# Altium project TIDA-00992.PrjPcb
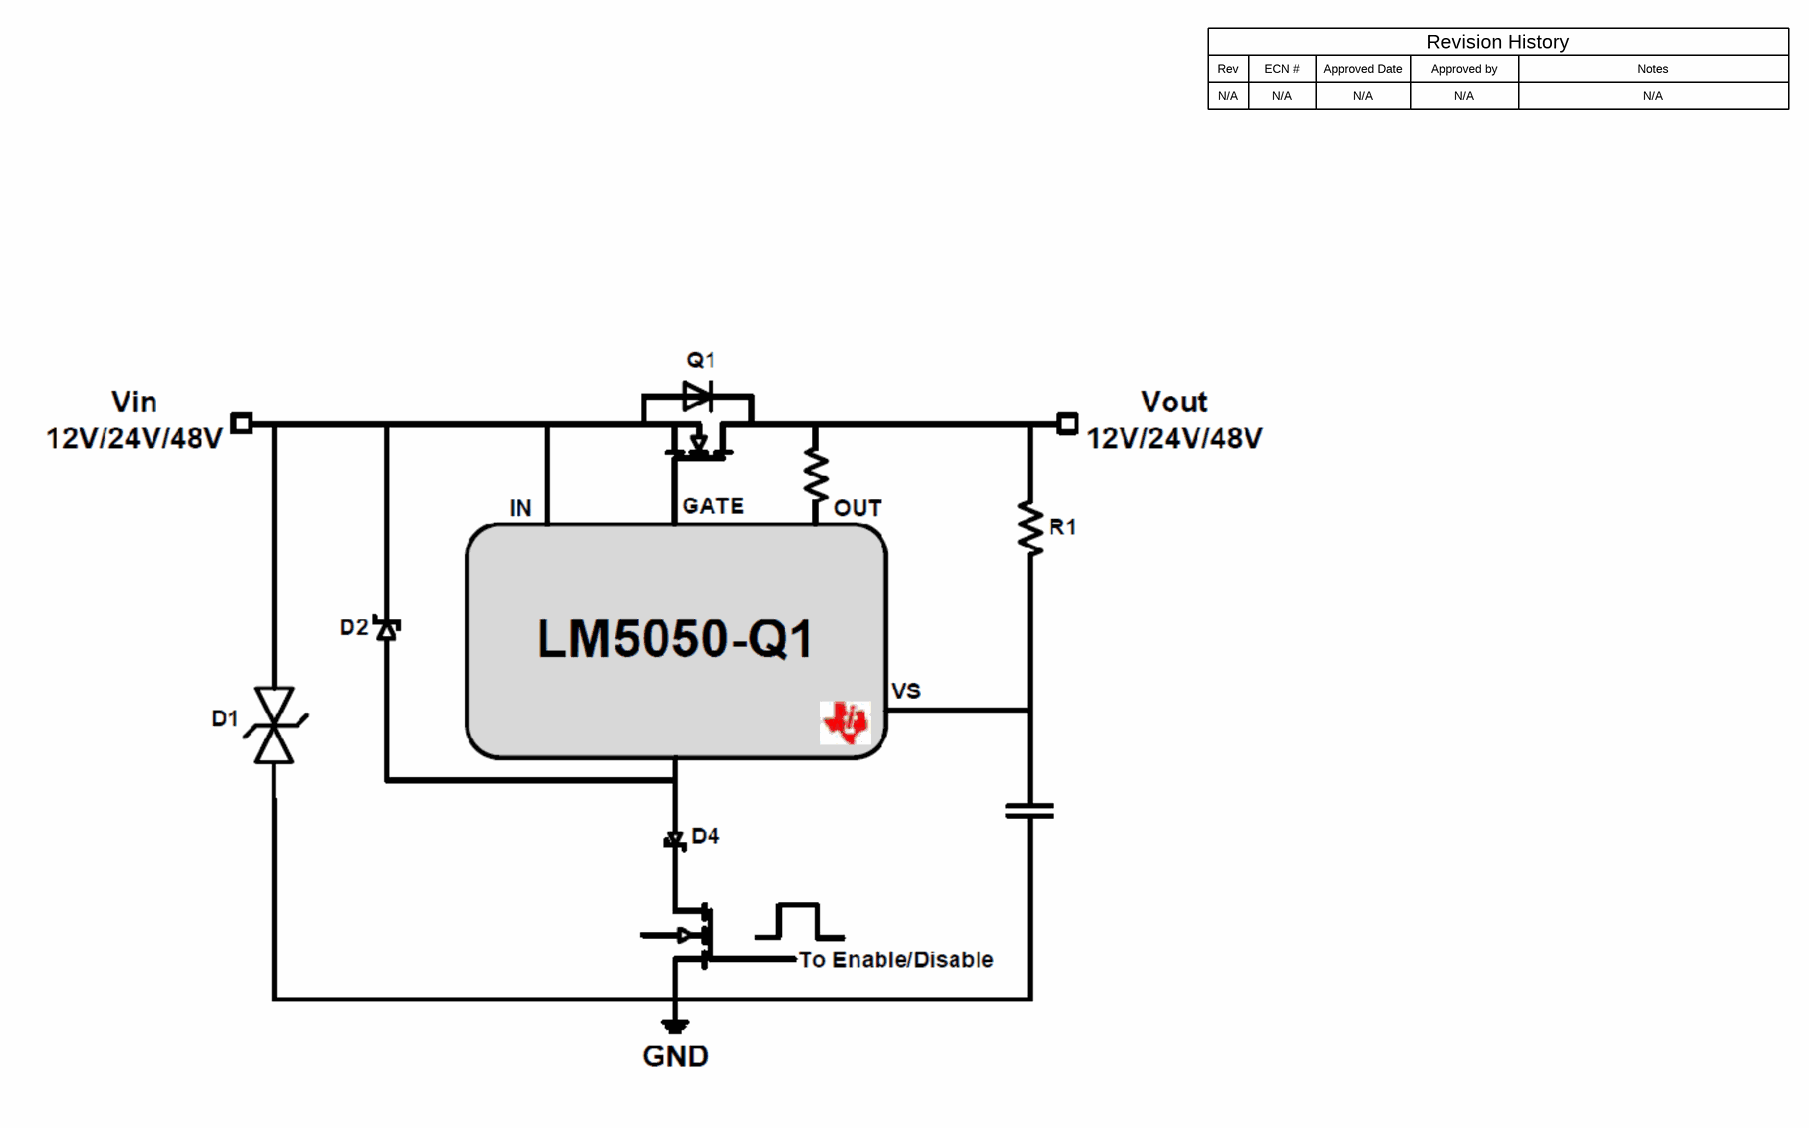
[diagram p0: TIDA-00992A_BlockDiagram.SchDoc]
CopyrightYear: 2016; EVM_orderable: TIDA-00992A; PCB_Layout: Rama Kambham; PCB_Rev: Rev A; PRJ_Customer: Public Release; PRJ_Engineer: Rama Kambham; PRJ_Number: TIDA-00992A; PRJ_Title: Automotive Reverse Polarity Protection; SCH_Rev: Rev A; TechSupport: http://www.ti.com/support; TID: N/A
3 sheets, 33 parts. Net scope: global (net labels, ports and power ports of the same name join across sheets).
Board file: TIDA-00992A_PCB.PcbDoc
Sheets:
  TIDA-00992A_BlockDiagram.SchDoc
  TIDA-00992A_AutomotiveReversePolarityProtection.SchDoc
  TIDA-00992A_Hardware.SchDoc

## Sheet TIDA-00992A_BlockDiagram.SchDoc: Block Diagram
size 431 x 279 mm; Date: Not shown in title block; ApprovedBy: Not shown in title block; CheckedBy: Not shown in title block; Author: Not shown in title block; CompanyName: Not shown in title block; DrawnBy: Rama Kambham; Engineer: Rama Kambham; Organization: Not shown in title block; Address1: Not shown in title block; Address2: Not shown in title block; Address3: Not shown in title block; Address4: Not shown in title block; DocumentNumber: 1; Revision: Use project parameter SCH_Rev; SheetNumber: 1; SheetTotal: 3; PageSetup: Record=PageOptions¦CenterHorizontal=True¦CenterVertical=True¦PrintScale=0.62¦XCorrection=1.00¦YCorrection=1.00¦PrintKind=0¦BorderSize=5000000¦LeftOffset=0¦BottomOffset=0¦Orientation=2¦PaperLength=1000¦PaperWidth=1000¦Scale=100¦PaperSource=15¦PrintQuality=600¦MediaType=1¦DitherType=10¦PrintScaleMode=1¦PaperKind=Letter

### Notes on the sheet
- Rev
- N/A
- ECN #
- Approved Date
- Approved by
- Revision History
- Notes

## Sheet TIDA-00992A_AutomotiveReversePolarityProtection.SchDoc: Schematic
size 431 x 279 mm; Date: Not shown in title block; ApprovedBy: Not shown in title block; CheckedBy: Not shown in title block; Author: Not shown in title block; CompanyName: Not shown in title block; DrawnBy: Rama Kambham; Engineer: Rama Kambham; Organization: Not shown in title block; Address1: Not shown in title block; Address2: Not shown in title block; Address3: Not shown in title block; Address4: Not shown in title block; DocumentNumber: 1; Revision: 01; SheetNumber: 2; SheetTotal: 3; PageSetup: Record=PageOptions¦CenterHorizontal=True¦CenterVertical=True¦PrintScale=1.00¦XCorrection=1.00¦YCorrection=1.00¦PrintKind=0¦BorderSize=5000000¦LeftOffset=0¦BottomOffset=0¦Orientation=2¦PaperLength=1000¦PaperWidth=1000¦Scale=100¦PaperSource=15¦PrintQuality=600¦MediaType=1¦DitherType=10¦PaperKind=Letter¦PrintScaleMode=1
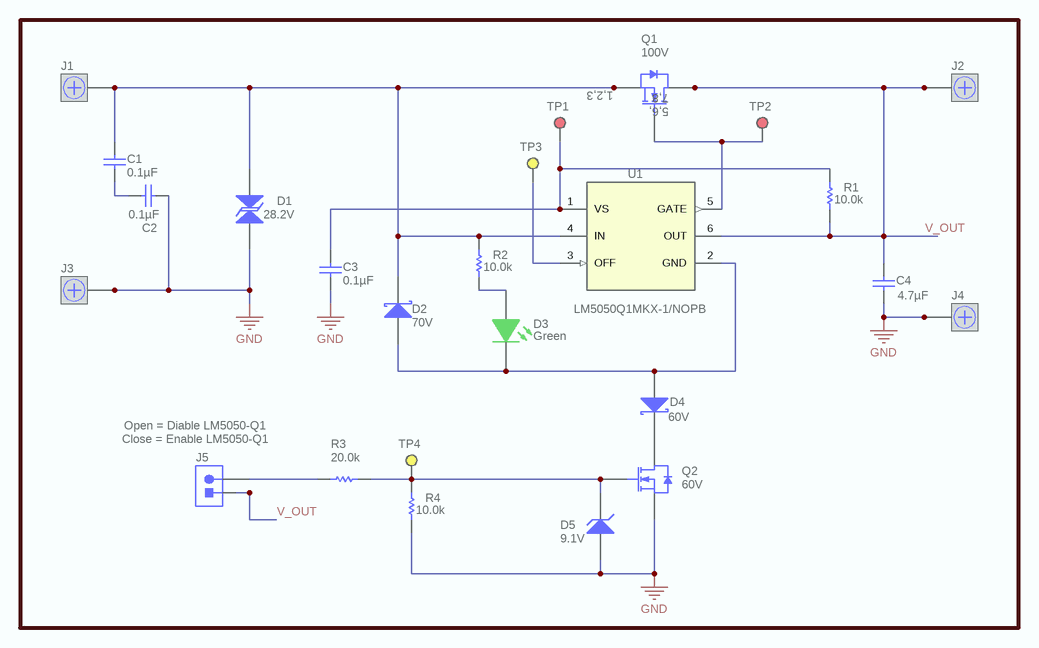
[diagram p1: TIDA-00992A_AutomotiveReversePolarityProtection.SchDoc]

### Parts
C1  ValueDisplayed: 0.1µF  [1206M]  (hidden comment: VJ1206Y104KBBAT4X)
C2  ValueDisplayed: 0.1µF  [1206]  (hidden comment: VJ1206Y104KBBAT4X)
C3  ValueDisplayed: 0.1µF  [0603S]  (hidden comment: GRM188R72A104KA35J)
C4  ValueDisplayed: 4.7µF  [1210_270]  (hidden comment: GRM32ER71K475KE14L)
D1  value 28.2V  [DO-214AB-Bi]  (hidden comment: 1.5SMC33CA-E3/57T)
D2  value 70V  [sod-323]  (hidden comment: BAS 170W E6327)
D3  value Green  [LNJx37x8_Green]  (hidden comment: LNJ337W83RA)
D4  value 60V  [SOD-323F]  (hidden comment: PMEG6010CEJ,115)
D5  value 9.1V  [sod-323]  (hidden comment: BZT52C9V1S-7-F)
J1  7693  [7693]  (value not drawn)
J2  7693  [7693]  (value not drawn)
J3  7693  [7693]  (value not drawn)
J4  7693  [7693]  (value not drawn)
J5  HTSW-102-07-G-S  [Samtec_HTSW-102-07-G-S]  (value not drawn)
Q1  value 100V  [TRANS_NexFET_Q5B]  (hidden comment: CSD19532Q5B)
Q2  value 60V  [SOT-23]  (hidden comment: NTR5198NLT1G)
R1  ValueDisplayed: 10.0k  [0402S]  (hidden comment: CRCW040210K0FKED)
R2  ValueDisplayed: 10.0k  [0402S]  (hidden comment: CRCW040210K0FKED)
R3  ValueDisplayed: 20.0k  [0603]  (hidden comment: RG1608P-203-B-T5)
R4  ValueDisplayed: 10.0k  [0402S]  (hidden comment: CRCW040210K0FKED)
TP1  5000  [Keystone5000]  (value not drawn)
TP2  5000  [Keystone5000]  (value not drawn)
TP3  5004  [Keystone5004]  (value not drawn)
TP4  5004  [Keystone5004]  (value not drawn)
U1  LM5050Q1MKX-1/NOPB  [DDC0006A_N]

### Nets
GND: C2.1 C3.2 C4.2 D1.1 D5.2(A) J3.1 J3.2 J3.3 J3.4 J4.1 J4.2 J4.3 J4.4 Q2.2(S) R4.1
V_OUT: C4.1 J2.1 J2.2 J2.3 J2.4 J5.1 Q1.5(D) Q1.6(D) Q1.7(D) Q1.8(D) R1.1 U1.6(OUT)
NetC1_1: C1.1 D1.2 D2.1(K) J1.1 J1.2 J1.3 J1.4 Q1.1(S) Q1.2(S) Q1.3(S) R2.2 U1.4(IN)
NetC1_2: C1.2 C2.2
NetC3_1: C3.1 R1.2 TP1.1 U1.1(VS)
NetD2_2: D2.2(A) D3.2(K) D4.2(A) U1.2(GND)
NetD3_1: D3.1(A) R2.1
NetD4_1: D4.1(K) Q2.3(D)
NetD5_1: D5.1(K) Q2.1(G) R3.2 R4.2 TP4.1
NetJ5_2: J5.2 R3.1
NetQ1_4: Q1.4(G) TP2.1 U1.5(GATE)
NetTP3_1: TP3.1 U1.3(OFF)

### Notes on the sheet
- (near J5) Open = Diable LM5050-Q1
- (near J5) Close = Enable LM5050-Q1

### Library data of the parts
C1 = VJ1206Y104KBBAT4X: CAP, CERM, 0.1 µF, 100 V, +/- 10%, X7R, 1206; Manufacturer: Vishay-Vitramon; Polarized: N; CompType: Capacitor; Value: 0.1uF; U/M: EA; Cap_F: 0.0000001; Tolerance_%: 10; Value1: Unknown; VDC_V: 100; Value2: 100V; TaMin_C: -55; TaMax_C: 125; Cap_Case: 1206; AEC Category: Q200
C2 = VJ1206Y104KBBAT4X: CAP, CERM, 0.1 µF, 100 V, +/- 10%, X7R, 1206; Manufacturer: Vishay-Vitramon; Polarized: N; CompType: Capacitor; Value: 0.1uF; U/M: EA; Cap_F: 0.0000001; Tolerance_%: 10; Value1: Unknown; VDC_V: 100; Value2: 100V; TaMin_C: -55; TaMax_C: 125; AEC Category: Q200
C3 = GRM188R72A104KA35J: CAP, CERM, 0.1 µF, 100 V, +/- 10%, X7R, 0603; Manufacturer: MuRata; Polarized: N; CompType: Capacitor; Value: 0.1uF; U/M: EA; Cap_F: 0.0000001; Tolerance_%: 10; Value1: Unknown; VDC_V: 100; Value2: 100V; TaMin_C: -55; TaMax_C: 125; Cap_Case: 0603; AEC Category: Q200
C4 = GRM32ER71K475KE14L: CAP, CERM, 4.7 µF, 80 V, +/- 10%, X7R, 1210; Manufacturer: MuRata; Polarized: N; CompType: Capacitor; Value: 4.7uF; U/M: EA; Cap_F: 0.0000047; Tolerance_%: 10; Value1: Unknown; VDC_V: 80; Value2: 80V; TaMin_C: -55; TaMax_C: 125; Cap_Case: 1210; AEC Category: Q200
D1 = 1.5SMC33CA-E3/57T: Diode, TVS, Bi, 28.2 V, 1500 W, DO-214AB (no polarity); Manufacturer: Vishay-Dale; U/M: EA; Power_W: 1500; Vr_V: 28.2; Value1: 1500W; RJA_CperW: 75; AEC Category: Q101
D2 = BAS 170W E6327: Diode, Schottky, 70 V, 0.07 A, AEC-Q101, SOD-323; Manufacturer: Infineon Technologies; U/M: EA; Vf_V: 1; Value1: 0.07A; Value2: 1V; Io_A: 0.07; Vr_V: 70; TJmax_C: 150; AEC Category: Q101; AEC Qualified: Y
D3 = LNJ337W83RA: LED, Green, SMD; Manufacturer: Panasonic; SymbolCreator: Altium; Vf_V: 1.95; Value2: 1.95V; Io_A: 0.005; Vr_V: 4; Ir_A: 1e-005; Tjmax_C: 85; Value1: W; U/M: EA
D4 = PMEG6010CEJ,115: Diode, Schottky, 60 V, 1 A, SOD-323F; Manufacturer: NXP Semiconductor; U/M: EA; Vf_V: 0.66; Value1: 1A; Value2: 0.66V; Io_A: 1; Vr_V: 60; TJmax_C: 150; AEC Category: Q101
D5 = BZT52C9V1S-7-F: Diode, Zener, 9.1 V, 200 mW, SOD-323; Manufacturer: Diodes Inc.; SymbolCreator: a0412235; U/M: EA; Power_W: 0.2; Vz_V: 9.1; Value1: 0.2W; RJA_CperW: 625; AEC Category: Q101
J1-J4 = 7693: Terminal screw, vertical, snap-in; Manufacturer: Keystone; SymbolCreator: a0412235; CompType: Screw Terminal
J5 = HTSW-102-07-G-S: Header, 100mil, 2x1, Gold, TH; Manufacturer: Samtec; SymbolCreator: a0412235
Q1 = CSD19532Q5B: MOSFET, N-CH, 100 V, 17 A, SON 5x6mm; Manufacturer: Texas Instruments; Alternate Manufacturer: None; U/M: EA; ChType: N; VdsMax_V: 100; Value1: ? ohm; Value2: 48 nC; QgTyp_nC: 48; Vgs_V: 20; IdsMax_A: 17; AEC Category: Q101
Q2 = NTR5198NLT1G: MOSFET, N-CH, 60 V, 1.7 A, SOT-23; Manufacturer: ON Semiconductor; Alternate Manufacturer: None; U/M: EA; ChType: N; VdsMax_V: 60; Value1: 0.205 ohm; Rdson45_ohm: 0.205; Value2: 5.1 nC; QgTyp_nC: 5.1; Vgs_V: 20; IdsMax_A: 1.7; AEC Category: Q101
R1 R2 R4 = CRCW040210K0FKED: RES, 10.0 k, 1%, 0.063 W, 0402; Manufacturer: Vishay-Dale; CompType: Resistor; Value: 10.0k; Res_ohm: 10000; Value_Code: 10k0; Tolerance_%: 1; Power_W: 0.063; Value2: 0.063W; VDC_V: 50; TempCo: 100 ppm/C; EIA_Code: E96; U/M: EA; AEC Category: Q200
R3 = RG1608P-203-B-T5: RES, 20.0 k, 0.1%, 0.1 W, 0603; Manufacturer: Susumu Co Ltd; CompType: Resistor; Value: 20.0k; Res_ohm: 20000; Value_Code: 20k0; Tolerance_%: 0.1; Value2: 0.1W; VDC_V: 75; TempCo: 25 ppm/C; EIA_Code: E192; U/M: EA; AEC Category: Q200
TP1 TP2 = 5000: Test Point, Miniature, Red, TH; Manufacturer: Keystone; CompType: Test Point Loop; ContactFinish: Silver
TP3 TP4 = 5004: Test Point, Miniature, Yellow, TH; Manufacturer: Keystone; CompType: Test Point Loop; ContactFinish: Silver
U1 = LM5050Q1MKX-1/NOPB: High Side OR-ing FET Controller, DDC0006A; Alternate PartNumber: LM5050Q1MK-1/NOPB; Manufacturer: Texas Instruments; SymbolCreator: Altium; CompType: IC; U/M: EA

## Sheet TIDA-00992A_Hardware.SchDoc: Hardware Schematic
size 431 x 279 mm; Date: Not shown in title block; ApprovedBy: Not shown in title block; CheckedBy: Not shown in title block; Author: Not shown in title block; CompanyName: Not shown in title block; DrawnBy: Rama Kambham; Engineer: Rama Kambham; Organization: Not shown in title block; Address1: Not shown in title block; Address2: Not shown in title block; Address3: Not shown in title block; Address4: Not shown in title block; DocumentNumber: 1; Revision: Use project parameter SCH_Rev; SheetNumber: 3; SheetTotal: 3; PageSetup: Record=PageOptions¦CenterHorizontal=True¦CenterVertical=True¦PrintScale=1.00¦XCorrection=1.00¦YCorrection=1.00¦PrintKind=0¦BorderSize=5000000¦LeftOffset=0¦BottomOffset=0¦Orientation=2¦PaperLength=1000¦PaperWidth=1000¦Scale=100¦PaperSource=15¦PrintQuality=600¦MediaType=1¦DitherType=10¦PaperKind=Letter¦PrintScaleMode=1
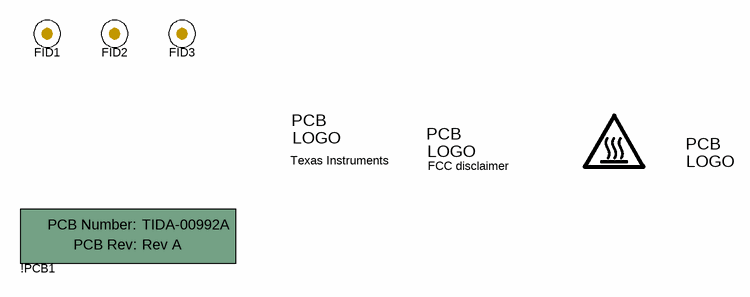
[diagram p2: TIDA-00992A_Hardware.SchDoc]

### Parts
!PCB1  Printed Circuit Board  (value not drawn)  (mechanical)
FID1  Fiducial  [Fiducial10-20]  (value not drawn)
FID2  Fiducial  [Fiducial10-20]  (value not drawn)
FID3  Fiducial  [Fiducial10-20]  (value not drawn)
Logo1  Texas Instruments  [TI_Stacked_SolderMask_Small]  (no BOM)
Logo3  FCC disclaimer  [FCC_disclaimer_stacked]  (no BOM)
LOGO4  CAUTION HOT SURFACE  [IEC_HotSurface_Small]  (value not drawn)  (no BOM)
Logo5  EU RoHS Exempt Logo  [EURoHS_Exempt_60mil]  (value not drawn)  (no BOM)

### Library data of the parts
!PCB1 = PCB: Manufacturer: Any; PartNumber: TIDA-00992A; SymbolCreator: a0412235
FID1-FID3 = Fiducial: Fiducial mark.  There is nothing to buy or mount.; SymbolCreator: codlsc
Logo1 = TI_Logo: Texas Instrument Corporate Signature; SymbolCreator: codlsc
Logo3 = FCC_disclaimer: SymbolCreator: codlsc
LOGO4 = IEC_HotSurface: IEC 61010-1 Hot Surface Warning; SymbolCreator: a0412235
Logo5 = EURoHS_Exempt: SymbolCreator: a0412235

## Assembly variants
001: not fitted FID1 FID2 FID3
